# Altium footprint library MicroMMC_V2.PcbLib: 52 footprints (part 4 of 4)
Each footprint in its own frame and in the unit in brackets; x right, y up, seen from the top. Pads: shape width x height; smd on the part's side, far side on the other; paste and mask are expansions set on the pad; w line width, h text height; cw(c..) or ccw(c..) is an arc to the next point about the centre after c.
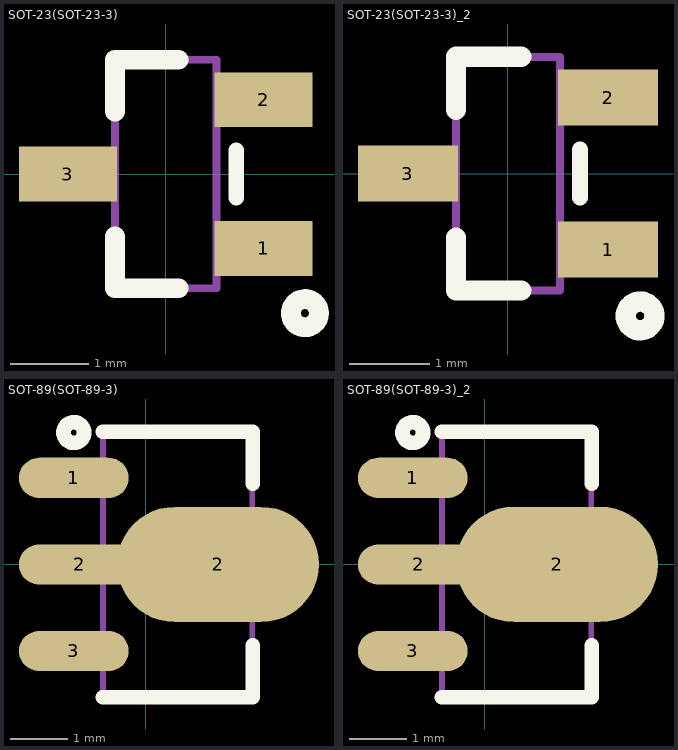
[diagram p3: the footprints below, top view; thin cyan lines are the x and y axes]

## SOT-23(SOT-23-3) [mm]
pads (3):
  rect 1.25x0.7 smd: 1(1.25,-0.95) 2(1.25,0.95) 3(-1.25,0)
Top Overlay:
  circle w0.254: c1.778,-1.778 r0.18
  lines w0.2: 0.9,-0.3 0.9,0.3
  lines w0.254: -0.65,-0.8 -0.65,-1.46 0.165,-1.46 ; 0.165,1.46 -0.65,1.46 ; -0.65,0.8 -0.65,1.46 ; -0.65,0.8 -0.65,1.46 ; -0.65,0.8 -0.65,1.46
Mechanical 13:
  lines w0.1: -0.65,-1.46 -0.65,1.46 ; -0.65,-1.46 0.65,-1.46 ; -0.65,-1.46 -0.65,1.46 ; -0.65,-1.46 0.65,-1.46 ; -0.65,-1.46 0.65,-1.46 ; -0.65,-1.46 -0.65,1.46 ; -0.65,1.46 0.65,1.46 ; -0.65,1.46 0.65,1.46 ; -0.65,1.46 0.65,1.46 ; 0.65,-1.46 0.65,1.46 ; 0.65,-1.46 0.65,1.46 ; 0.65,-1.46 0.65,1.46
3D body "SOT-23.step": height 1.3, standoff 0, extent -1.5,-1.5 1.5,1.5

## SOT-23(SOT-23-3)_2 [mm]
pads (3):
  rect 1.25x0.7 smd: 1(1.25,-0.95) 2(1.25,0.95) 3(-1.25,0)
Top Overlay:
  circle w0.254: c1.651,-1.778 r0.18
  lines w0.2: 0.9,-0.3 0.9,0.3
  lines w0.254: -0.65,-0.8 -0.65,-1.46 0.165,-1.46 ; 0.165,1.46 -0.65,1.46 ; -0.65,0.8 -0.65,1.46 ; -0.65,0.8 -0.65,1.46 ; -0.65,0.8 -0.65,1.46
Mechanical 13:
  lines w0.1: -0.65,-1.46 -0.65,1.46 ; -0.65,-1.46 0.65,-1.46 ; -0.65,-1.46 -0.65,1.46 ; -0.65,-1.46 0.65,-1.46 ; -0.65,-1.46 0.65,-1.46 ; -0.65,-1.46 -0.65,1.46 ; -0.65,1.46 0.65,1.46 ; -0.65,1.46 0.65,1.46 ; -0.65,1.46 0.65,1.46 ; 0.65,-1.46 0.65,1.46 ; 0.65,-1.46 0.65,1.46 ; 0.65,-1.46 0.65,1.46
3D body "SOT-23.step": height 1.3, standoff 0, extent -1.5,-1.5 1.5,1.5

## SOT-89(SOT-89-3) [mm]
pads (4):
  oval 1.9x0.7 smd: 1(-1.25,1.5) 3(-1.25,-1.5)
  oval 2.1x0.7 smd: 2(-1.15,0)
  oval 3.5x2 smd: 2(1.25,0)
Top Overlay:
  circle w0.254: c-1.25,2.286 r0.18
  lines w0.254: -0.75,-2.3 1.85,-2.3 1.85,-1.4 ; -0.75,2.3 1.85,2.3 1.85,1.4
Mechanical 13:
  lines w0.1: -0.745,-2.3 1.845,-2.3 1.845,2.3 -0.745,2.3 -0.745,-2.3
3D body "SOT-89-3.STEP": height 1.51, standoff 0, extent -1.8,-2.25 2.5,2.25

## SOT-89(SOT-89-3)_2 [mm]
pads (4):
  oval 1.9x0.7 smd: 1(-1.25,1.5) 3(-1.25,-1.5)
  oval 2.1x0.7 smd: 2(-1.15,0)
  oval 3.5x2 smd: 2(1.25,0)
Top Overlay:
  circle w0.254: c-1.25,2.286 r0.18
  lines w0.254: -0.75,-2.3 1.85,-2.3 1.85,-1.4 ; -0.75,2.3 1.85,2.3 1.85,1.4
Mechanical 13:
  lines w0.1: -0.745,-2.3 -0.745,2.3 1.845,2.3 1.845,-2.3 -0.745,-2.3
3D body "SOT-89-3.STEP": height 1.51, standoff 0, extent -1.8,-2.25 2.5,2.25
